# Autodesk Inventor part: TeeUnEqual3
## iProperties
Author: Administrator
Shininess: 86.0
PropertySet Name: _Private Model Information
Created: 2001-01
Part Number: TeeUnEqual3
Document SubType Name: Modeling
Designer: Administrator
Control State: 0
Master: False
Checked Out: False
PropertySet Name: Design Tracking Control
Density: 0.0
Volumn: 0.0
Area: 0.0
PropertySet Name: Model Information
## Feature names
1. SpoolRevolve [Revolution]
2. BranceRevolve [Revolution]
3. SpoolCleanOut [Revolution]
4. BranchCleanOut [Revolution]
5. Fillet1
6. Fillet2
7. Revolution7
8. Revolution8
